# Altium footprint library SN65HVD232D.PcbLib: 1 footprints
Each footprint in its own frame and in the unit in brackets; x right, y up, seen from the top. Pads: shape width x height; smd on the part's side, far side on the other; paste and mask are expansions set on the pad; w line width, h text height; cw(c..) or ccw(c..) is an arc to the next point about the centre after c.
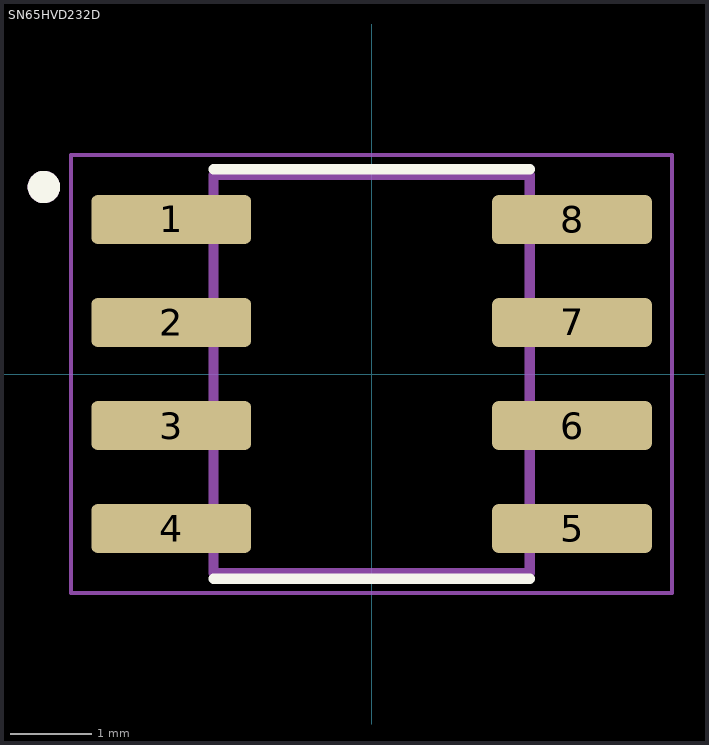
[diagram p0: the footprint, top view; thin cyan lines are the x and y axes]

## SN65HVD232D [mm]
pads (8):
  rrect25% 1.97x0.6 smd: 1(-2.47,1.905) 2(-2.47,0.635) 3(-2.47,-0.635) 4(-2.47,-1.905) 5(2.47,-1.905) 6(2.47,-0.635) 7(2.47,0.635) 8(2.47,1.905)
Top Overlay:
  circle w0.2: c-4.04,2.305 r0.1
  lines w0.127: -1.95,-2.525 1.95,-2.525 ; -1.95,2.525 1.95,2.525
Mechanical 13:
  circle w0.2: c-4.04,2.305 r0.1
  lines w0.127: -1.95,-2.452 -1.95,2.452 1.95,2.452 1.95,-2.452 -1.95,-2.452
Mechanical 15:
  lines w0.05: -3.705,-2.702 -3.705,2.702 3.705,2.702 3.705,-2.702 -3.705,-2.702
3D body "step_temp.STEP": height 1.75, standoff 0, extent -2.997,-2.451 2.997,2.451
